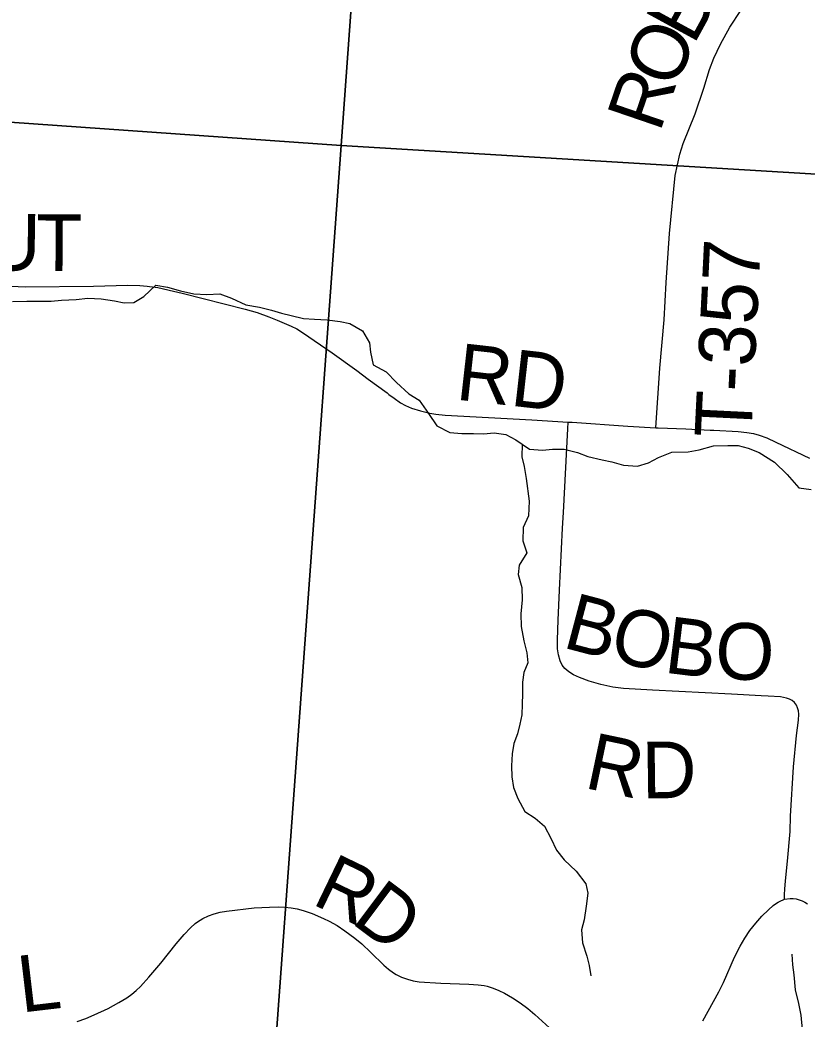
# Model space of a CAD drawing. Extents: x 39.8 to 73.8, y 13 to 35.
# Drawn here: x 45.185 to 45.973, y 31.251 to 32.252 of the extents above; entities that cross this region are included whole.
import ezdxf

# ---------------------------------------------------------------- set-up
doc = ezdxf.new("R2010")
doc.units = 0
for name, color, linetype in [('GM_X_Corporation', 7, 'Continuous'), ('GM_X_Minor_River', 7, 'Continuous'), ('GM_X_Township_Road', 7, 'Continuous'), ('GM_X_Township_Road_Text', 7, 'Continuous')]:
    doc.layers.add(name, color=color, linetype=linetype)

msp = doc.modelspace()

# ---------------------------------------------------------------- linework, layer by layer
at = {"layer": 'GM_X_Corporation'}
for points in [[(45.5809, 33.1493), (45.5069, 32.1262), (44.516, 32.1957), (44.5795, 33.2157)], [(45.5809, 33.1493), (46.5718, 33.0824), (46.4973, 32.0662), (45.5069, 32.1262)], [(44.516, 32.1957), (45.5069, 32.1262), (45.4314, 31.091), (44.4392, 31.1377)], [(46.4973, 32.0662), (46.4309, 31.0306), (45.4314, 31.091), (45.5069, 32.1262)]]:
    msp.add_lwpolyline(points, close=True, dxfattribs=at)
at = {"layer": 'GM_X_Minor_River'}
for p, q in [((45.6883, 31.8268), (45.6879, 31.8143)), ((45.6879, 31.8143), (45.6902, 31.8044)), ((45.6902, 31.8044), (45.6921, 31.7926)), ((45.6921, 31.7926), (45.6953, 31.7699)), ((45.6953, 31.7699), (45.6946, 31.7551)), ((45.6946, 31.7551), (45.6893, 31.7433)), ((45.6893, 31.7433), (45.689, 31.73)), ((45.689, 31.73), (45.6928, 31.7179)), ((45.6928, 31.7179), (45.6853, 31.7058)), ((45.6853, 31.7058), (45.6842, 31.6963)), ((45.6842, 31.6963), (45.6877, 31.6834)), ((45.6877, 31.6834), (45.6881, 31.6709)), ((45.6881, 31.6709), (45.6867, 31.6568)), ((45.6867, 31.6568), (45.6871, 31.6443)), ((45.6871, 31.6443), (45.6898, 31.6299)), ((45.6898, 31.6299), (45.6929, 31.6178)), ((45.6929, 31.6178), (45.6937, 31.6079)), ((45.6937, 31.6079), (45.6899, 31.598)), ((45.6899, 31.598), (45.6885, 31.5885)), ((45.6885, 31.5885), (45.6885, 31.5768)), ((45.6885, 31.5768), (45.6882, 31.5665)), ((45.6882, 31.5665), (45.6878, 31.5559)), ((45.6878, 31.5559), (45.686, 31.5464)), ((45.686, 31.5464), (45.6834, 31.5366)), ((45.6834, 31.5366), (45.68, 31.5271)), ((45.68, 31.5271), (45.6782, 31.5168)), ((45.6782, 31.5168), (45.6775, 31.5047)), ((45.6775, 31.5047), (45.6779, 31.4937)), ((45.6779, 31.4937), (45.6794, 31.4831)), ((45.6794, 31.4831), (45.6837, 31.4721)), ((45.6837, 31.4721), (45.6909, 31.4588)), ((45.6909, 31.4588), (45.7012, 31.4524)), ((45.7012, 31.4524), (45.7107, 31.4441)), ((45.7107, 31.4441), (45.7168, 31.4323)), ((45.7168, 31.4323), (45.7225, 31.4202)), ((45.7225, 31.4202), (45.7301, 31.4104)), ((45.7301, 31.4104), (45.7423, 31.399)), ((45.7423, 31.399), (45.7518, 31.3866)), ((45.7518, 31.3866), (45.7541, 31.3771)), ((45.7541, 31.3771), (45.7523, 31.3642)), ((45.7523, 31.3642), (45.7501, 31.3505)), ((45.7501, 31.3505), (45.7475, 31.3403)), ((45.7475, 31.3403), (45.7487, 31.3274)), ((45.7487, 31.3274), (45.7529, 31.3141)), ((45.7529, 31.3141), (45.7552, 31.3046)), ((45.7552, 31.3046), (45.7571, 31.2944))]:
    msp.add_line(p, q, dxfattribs=at)
for points in [[(45.1779, 31.9697), (45.1923, 31.9701), (45.2165, 31.9702), (45.2271, 31.971), (45.2415, 31.9718), (45.2533, 31.973), (45.2665, 31.9726), (45.2801, 31.9704), (45.2896, 31.9685), (45.2995, 31.9689), (45.3093, 31.9747), (45.3214, 31.9861), (45.3331, 31.9842), (45.346, 31.9805), (45.3596, 31.9775), (45.3725, 31.9768), (45.3854, 31.9776), (45.3971, 31.973), (45.4116, 31.9663), (45.4252, 31.964), (45.4373, 31.961), (45.4472, 31.958), (45.457, 31.9558), (45.4692, 31.9528), (45.4802, 31.9521), (45.493, 31.9513), (45.5059, 31.9499), (45.5158, 31.9476), (45.5283, 31.9405), (45.5352, 31.9283), (45.5363, 31.9189), (45.539, 31.9063), (45.5519, 31.8992), (45.5622, 31.8886), (45.5748, 31.8772), (45.585, 31.8708), (45.5945, 31.8576), (45.6029, 31.8451), (45.6158, 31.8387), (45.6279, 31.8376), (45.6393, 31.8376), (45.6495, 31.8373), (45.6601, 31.8381), (45.6719, 31.8366), (45.6817, 31.8313), (45.6954, 31.8219), (45.7087, 31.8208), (45.7185, 31.8219), (45.7302, 31.822), (45.7435, 31.8186), (45.7538, 31.8145), (45.7682, 31.8111), (45.778, 31.8092), (45.7898, 31.8058), (45.8038, 31.8048), (45.8147, 31.8082), (45.8246, 31.8135), (45.8382, 31.8189), (45.8545, 31.8193), (45.8654, 31.8213), (45.8798, 31.8251), (45.8942, 31.8255), (45.9044, 31.8256), (45.9146, 31.8229), (45.9256, 31.8184), (45.9408, 31.809), (45.9534, 31.7965), (45.9652, 31.7833), (45.9777, 31.7814)], [(45.958, 31.1607), (45.9602, 31.171), (45.964, 31.1839), (45.9669, 31.1995), (45.968, 31.2101), (45.9683, 31.2234), (45.969, 31.2404), (45.9674, 31.2548), (45.9651, 31.2666), (45.962, 31.2802), (45.9605, 31.2954), (45.9593, 31.3053), (45.9585, 31.3159)]]:
    msp.add_lwpolyline(points, dxfattribs=at)
at = {"layer": 'GM_X_Township_Road'}
for points in [[(45.8219, 31.8432), (45.8261, 31.9031), (45.8303, 31.9514), (45.8324, 31.9889), (45.8358, 32.0379), (45.8413, 32.096), (45.846, 32.1175), (45.8493, 32.128), (45.8613, 32.1577), (45.87, 32.1835), (45.8759, 32.2022), (45.8802, 32.2137), (45.8867, 32.2275), (45.8962, 32.2445), (45.907, 32.2613), (45.9177, 32.2759), (45.9381, 32.2986), (45.9495, 32.3099), (45.9588, 32.3198), (45.9684, 32.3291), (45.9701, 32.3304)], [(45.1286, 31.9876), (45.1907, 31.9845), (45.2589, 31.9851), (45.2931, 31.986), (45.3055, 31.9858), (45.3126, 31.9852), (45.3152, 31.9849), (45.3182, 31.9846), (45.3234, 31.9837), (45.3278, 31.9828), (45.3347, 31.9812), (45.3476, 31.978), (45.4107, 31.9622), (45.4229, 31.9588), (45.4344, 31.9546), (45.4428, 31.9512), (45.4568, 31.9452), (45.4625, 31.9423), (45.4682, 31.9389), (45.4979, 31.9185), (45.5228, 31.9007), (45.5341, 31.8921), (45.5529, 31.8784), (45.5548, 31.8767), (45.56, 31.8731), (45.5664, 31.8684), (45.5713, 31.8656), (45.5774, 31.8629), (45.5865, 31.8602), (45.5956, 31.8581), (45.6017, 31.8571), (45.611, 31.8561), (45.6978, 31.8511), (45.7342, 31.849), (45.7381, 31.8488), (45.7939, 31.8449), (45.8219, 31.8432), (45.8245, 31.8431), (45.8522, 31.8422), (45.8764, 31.841), (45.8802, 31.8408)], [(45.951, 31.371), (45.9509, 31.3759), (45.9511, 31.381), (45.9519, 31.3896), (45.954, 31.4091), (45.9565, 31.4389), (45.957, 31.4542), (45.96, 31.5038), (45.9629, 31.5349), (45.965, 31.5503), (45.9652, 31.5565), (45.9648, 31.5596), (45.964, 31.5626), (45.9627, 31.5655), (45.9609, 31.568), (45.9586, 31.57), (45.9559, 31.5715), (45.9529, 31.5725), (45.9468, 31.5737), (45.9345, 31.5746), (45.9274, 31.5749), (45.8978, 31.5764), (45.8187, 31.5805), (45.7895, 31.5822), (45.779, 31.5836), (45.7669, 31.5863), (45.7552, 31.5896), (45.7457, 31.593), (45.7397, 31.5959), (45.7348, 31.5988), (45.731, 31.6021), (45.7284, 31.6056), (45.7263, 31.6099), (45.7245, 31.6157), (45.7235, 31.6218), (45.7236, 31.6309), (45.7241, 31.6507), (45.7255, 31.6806), (45.7287, 31.7427), (45.7296, 31.7584), (45.7338, 31.8424), (45.7342, 31.849)], [(45.8802, 31.8408), (45.9043, 31.8395), (45.9132, 31.8386), (45.9198, 31.8376), (45.9256, 31.836), (45.933, 31.8331), (45.9422, 31.829), (45.9758, 31.8128)], [(45.8692, 31.2493), (45.8852, 31.2782), (45.8898, 31.2875), (45.9009, 31.313), (45.9064, 31.324), (45.9111, 31.3321), (45.9163, 31.3398), (45.9221, 31.3471), (45.9283, 31.354), (45.9349, 31.3605), (45.9396, 31.3647), (45.942, 31.3665), (45.9446, 31.3682), (45.9471, 31.3696), (45.9496, 31.3705), (45.951, 31.371), (45.9564, 31.3719), (45.9595, 31.3718), (45.9625, 31.3714), (45.9655, 31.3705), (45.9684, 31.3694), (45.9712, 31.368), (45.9738, 31.3664)], [(45.2427, 31.2486), (45.2514, 31.2516), (45.2598, 31.2551), (45.2736, 31.2616), (45.2844, 31.2675), (45.2923, 31.2724), (45.2972, 31.2759), (45.3017, 31.2795), (45.306, 31.2837), (45.3143, 31.2929), (45.3263, 31.307), (45.3416, 31.3263), (45.3496, 31.3358), (45.356, 31.3425), (45.3607, 31.3466), (45.3632, 31.3485), (45.3685, 31.3517), (45.3741, 31.3544), (45.3799, 31.3565), (45.3859, 31.3581), (45.392, 31.3591), (45.4197, 31.3624), (45.4352, 31.3632), (45.4445, 31.3634), (45.4507, 31.3631), (45.4568, 31.3624), (45.4629, 31.3613), (45.469, 31.3597), (45.4778, 31.3567), (45.4892, 31.3519), (45.4948, 31.3492), (45.5028, 31.3446), (45.5106, 31.3395), (45.5205, 31.3321), (45.5276, 31.3262), (45.5366, 31.3178), (45.5498, 31.305), (45.5544, 31.301), (45.5594, 31.2973), (45.562, 31.2957), (45.5647, 31.2942), (45.5675, 31.2929), (45.5733, 31.2908), (45.5792, 31.2892), (45.5852, 31.2884), (45.6068, 31.2871), (45.6348, 31.2861), (45.6441, 31.2853), (45.6502, 31.2845), (45.6532, 31.2839), (45.6592, 31.282), (45.6649, 31.2797), (45.6706, 31.277), (45.6786, 31.2723), (45.6863, 31.2671), (45.6937, 31.2616), (45.7008, 31.2555), (45.7191, 31.2388)]]:
    msp.add_lwpolyline(points, dxfattribs=at)

# ---------------------------------------------------------------- texts
at = {"layer": 'GM_X_Township_Road_Text'}
for s, height, rotation, p in [('B', 0.0568, 61.4219, (45.8598, 32.2258)), ('O', 0.0568, 66.579, (45.8406, 32.1812)), ('R', 0.0568, 71.096, (45.8259, 32.1381)), ('U', 0.0568, 359.1761, (45.1508, 32.0013)), ('T', 0.0568, 359.5711, (45.2012, 32.0005)), ('T-357', 0.05682, 87.193, (45.9175, 31.8322)), ('RD', 0.05682, 353.6052, (45.6207, 31.8717)), ('B', 0.0568, 345.1988, (45.7273, 31.6236)), ('O', 0.0568, 346.2529, (45.7735, 31.6114)), ('B', 0.0568, 352.9679, (45.8292, 31.5982)), ('O', 0.0568, 357.7069, (45.8806, 31.5921)), ('R', 0.0568, 348.1037, (45.7491, 31.4828)), ('D', 0.0568, 0.796, (45.8082, 31.4719)), ('R', 0.0568, 334.2309, (45.4763, 31.3669)), ('D', 0.0568, 323.0893, (45.5158, 31.3481)), ('L', 0.0568, 6.7257, (45.1867, 31.2574))]:
    msp.add_text(s, height=height, rotation=rotation, dxfattribs=at).set_placement(p)

doc.saveas('drawing.dxf')
